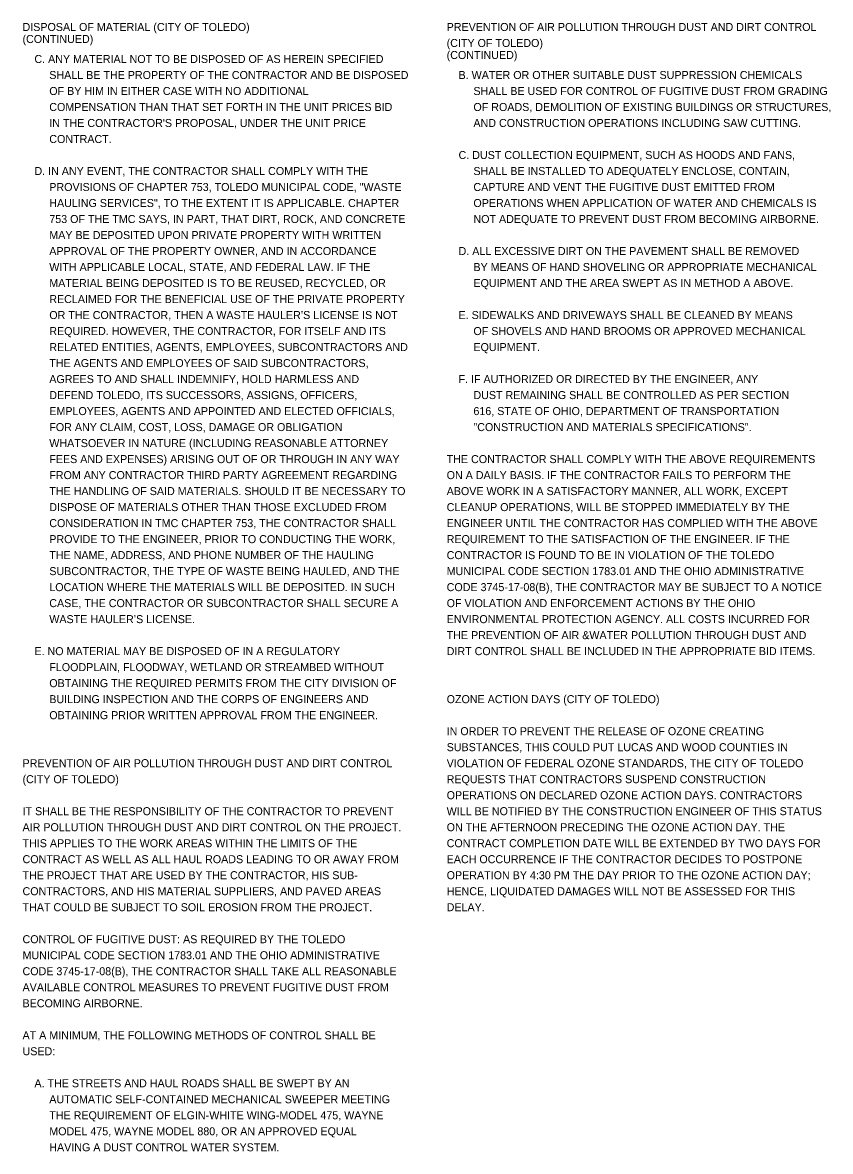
# Model space of a CAD drawing. Extents: x -15.9 to 34, y 0 to 22.
# Drawn here: x -15.92 to -1.79, y 1.02 to 20.77 of the extents above; entities that cross this region are included whole.
import ezdxf

# ---------------------------------------------------------------- set-up
doc = ezdxf.new("R2010")
doc.units = 0
doc.layers.add('SH_Text', color=7, linetype='Continuous')

msp = doc.modelspace()

# ---------------------------------------------------------------- texts
at = {"layer": 'SH_Text'}
for s, p in [('DISPOSAL OF MATERIAL (CITY OF TOLEDO)', (-15.921, 20.621)), ('PREVENTION OF AIR POLLUTION THROUGH DUST AND DIRT CONTROL', (-8.501, 20.621)), ('(CONTINUED)', (-15.921, 20.411)), ('(CITY OF TOLEDO)', (-8.501, 20.341)), ('    C. ANY MATERIAL NOT TO BE DISPOSED OF AS HEREIN SPECIFIED', (-15.921, 20.061)), ('(CONTINUED)', (-8.501, 20.131)), ('         SHALL BE THE PROPERTY OF THE CONTRACTOR AND BE DISPOSED', (-15.921, 19.781)), ('    B. WATER OR OTHER SUITABLE DUST SUPPRESSION CHEMICALS', (-8.501, 19.781)), ('         OF BY HIM IN EITHER CASE WITH NO ADDITIONAL', (-15.921, 19.501)), ('         SHALL BE USED FOR CONTROL OF FUGITIVE DUST FROM GRADING', (-8.501, 19.501)), ('         COMPENSATION THAN THAT SET FORTH IN THE UNIT PRICES BID', (-15.921, 19.221)), ('         OF ROADS, DEMOLITION OF EXISTING BUILDINGS OR STRUCTURES,', (-8.501, 19.221)), ("         IN THE CONTRACTOR'S PROPOSAL, UNDER THE UNIT PRICE", (-15.921, 18.941)), ('         AND CONSTRUCTION OPERATIONS INCLUDING SAW CUTTING.', (-8.501, 18.941)), ('         CONTRACT.', (-15.921, 18.661)), ('    C. DUST COLLECTION EQUIPMENT, SUCH AS HOODS AND FANS, ', (-8.501, 18.381)), ('    D. IN ANY EVENT, THE CONTRACTOR SHALL COMPLY WITH THE', (-15.921, 18.101)), ('         SHALL BE INSTALLED TO ADEQUATELY ENCLOSE, CONTAIN,', (-8.501, 18.101)), ('         PROVISIONS OF CHAPTER 753, TOLEDO MUNICIPAL CODE, "WASTE', (-15.921, 17.821)), ('         CAPTURE AND VENT THE FUGITIVE DUST EMITTED FROM ', (-8.501, 17.821)), ('         HAULING SERVICES", TO THE EXTENT IT IS APPLICABLE. CHAPTER', (-15.921, 17.541)), ('         OPERATIONS WHEN APPLICATION OF WATER AND CHEMICALS IS ', (-8.501, 17.541)), ('         753 OF THE TMC SAYS, IN PART, THAT DIRT, ROCK, AND CONCRETE', (-15.921, 17.261)), ('         NOT ADEQUATE TO PREVENT DUST FROM BECOMING AIRBORNE.', (-8.501, 17.261)), ('         MAY BE DEPOSITED UPON PRIVATE PROPERTY WITH WRITTEN', (-15.921, 16.981)), ('         APPROVAL OF THE PROPERTY OWNER, AND IN ACCORDANCE', (-15.921, 16.701)), ('    D. ALL EXCESSIVE DIRT ON THE PAVEMENT SHALL BE REMOVED', (-8.501, 16.701)), ('         WITH APPLICABLE LOCAL, STATE, AND FEDERAL LAW. IF THE', (-15.921, 16.421)), ('         BY MEANS OF HAND SHOVELING OR APPROPRIATE MECHANICAL ', (-8.501, 16.421)), ('         MATERIAL BEING DEPOSITED IS TO BE REUSED, RECYCLED, OR', (-15.921, 16.141)), ('         EQUIPMENT AND THE AREA SWEPT AS IN METHOD A ABOVE.', (-8.501, 16.141)), ('         RECLAIMED FOR THE BENEFICIAL USE OF THE PRIVATE PROPERTY', (-15.921, 15.861)), ('         OR THE CONTRACTOR, THEN A WASTE HAULER’S LICENSE IS NOT', (-15.921, 15.581)), ('    E. SIDEWALKS AND DRIVEWAYS SHALL BE CLEANED BY MEANS ', (-8.501, 15.581)), ('         REQUIRED. HOWEVER, THE CONTRACTOR, FOR ITSELF AND ITS', (-15.921, 15.301)), ('         OF SHOVELS AND HAND BROOMS OR APPROVED MECHANICAL ', (-8.501, 15.301)), ('         RELATED ENTITIES, AGENTS, EMPLOYEES, SUBCONTRACTORS AND', (-15.921, 15.021)), ('         EQUIPMENT.', (-8.501, 15.021)), ('         THE AGENTS AND EMPLOYEES OF SAID SUBCONTRACTORS,', (-15.921, 14.741)), ('         AGREES TO AND SHALL INDEMNIFY, HOLD HARMLESS AND', (-15.921, 14.461)), ('    F. IF AUTHORIZED OR DIRECTED BY THE ENGINEER, ANY ', (-8.501, 14.461)), ('         DEFEND TOLEDO, ITS SUCCESSORS, ASSIGNS, OFFICERS,', (-15.921, 14.181)), ('         DUST REMAINING SHALL BE CONTROLLED AS PER SECTION ', (-8.501, 14.181)), ('         EMPLOYEES, AGENTS AND APPOINTED AND ELECTED OFFICIALS,', (-15.921, 13.901)), ('         616, STATE OF OHIO, DEPARTMENT OF TRANSPORTATION ', (-8.501, 13.901)), ('         FOR ANY CLAIM, COST, LOSS, DAMAGE OR OBLIGATION', (-15.921, 13.621)), ('         "CONSTRUCTION AND MATERIALS SPECIFICATIONS".', (-8.501, 13.621)), ('         WHATSOEVER IN NATURE (INCLUDING REASONABLE ATTORNEY', (-15.921, 13.341)), ('         FEES AND EXPENSES) ARISING OUT OF OR THROUGH IN ANY WAY', (-15.921, 13.061)), ('THE CONTRACTOR SHALL COMPLY WITH THE ABOVE REQUIREMENTS', (-8.501, 13.061)), ('         FROM ANY CONTRACTOR THIRD PARTY AGREEMENT REGARDING', (-15.921, 12.781)), ('ON A DAILY BASIS. IF THE CONTRACTOR FAILS TO PERFORM THE', (-8.501, 12.781)), ('         THE HANDLING OF SAID MATERIALS. SHOULD IT BE NECESSARY TO', (-15.921, 12.501)), ('ABOVE WORK IN A SATISFACTORY MANNER, ALL WORK, EXCEPT', (-8.501, 12.501)), ('         DISPOSE OF MATERIALS OTHER THAN THOSE EXCLUDED FROM', (-15.921, 12.221)), ('CLEANUP OPERATIONS, WILL BE STOPPED IMMEDIATELY BY THE', (-8.501, 12.221)), ('         CONSIDERATION IN TMC CHAPTER 753, THE CONTRACTOR SHALL', (-15.921, 11.941)), ('ENGINEER UNTIL THE CONTRACTOR HAS COMPLIED WITH THE ABOVE', (-8.501, 11.941)), ('         PROVIDE TO THE ENGINEER, PRIOR TO CONDUCTING THE WORK,', (-15.921, 11.661)), ('REQUIREMENT TO THE SATISFACTION OF THE ENGINEER. IF THE', (-8.501, 11.661)), ('         THE NAME, ADDRESS, AND PHONE NUMBER OF THE HAULING', (-15.921, 11.381)), ('CONTRACTOR IS FOUND TO BE IN VIOLATION OF THE TOLEDO', (-8.501, 11.381)), ('         SUBCONTRACTOR, THE TYPE OF WASTE BEING HAULED, AND THE', (-15.921, 11.101)), ('MUNICIPAL CODE SECTION 1783.01 AND THE OHIO ADMINISTRATIVE', (-8.501, 11.101)), ('         LOCATION WHERE THE MATERIALS WILL BE DEPOSITED. IN SUCH', (-15.921, 10.821)), ('CODE 3745-17-08(B), THE CONTRACTOR MAY BE SUBJECT TO A NOTICE', (-8.501, 10.821)), ('         CASE, THE CONTRACTOR OR SUBCONTRACTOR SHALL SECURE A', (-15.921, 10.541)), ('OF VIOLATION AND ENFORCEMENT ACTIONS BY THE OHIO', (-8.501, 10.541)), ('         WASTE HAULER’S LICENSE.', (-15.921, 10.261)), ('ENVIRONMENTAL PROTECTION AGENCY. ALL COSTS INCURRED FOR', (-8.501, 10.261)), ('THE PREVENTION OF AIR &WATER POLLUTION THROUGH DUST AND', (-8.501, 9.981)), ('    E. NO MATERIAL MAY BE DISPOSED OF IN A REGULATORY', (-15.921, 9.701)), ('DIRT CONTROL SHALL BE INCLUDED IN THE APPROPRIATE BID ITEMS.', (-8.501, 9.701)), ('         FLOODPLAIN, FLOODWAY, WETLAND OR STREAMBED WITHOUT', (-15.921, 9.421)), ('         OBTAINING THE REQUIRED PERMITS FROM THE CITY DIVISION OF', (-15.921, 9.141)), ('         BUILDING INSPECTION AND THE CORPS OF ENGINEERS AND', (-15.921, 8.861)), ('OZONE ACTION DAYS (CITY OF TOLEDO)', (-8.501, 8.861)), ('         OBTAINING PRIOR WRITTEN APPROVAL FROM THE ENGINEER.', (-15.921, 8.581)), ('IN ORDER TO PREVENT THE RELEASE OF OZONE CREATING', (-8.501, 8.301)), ('SUBSTANCES, THIS COULD PUT LUCAS AND WOOD COUNTIES IN', (-8.501, 8.021)), ('PREVENTION OF AIR POLLUTION THROUGH DUST AND DIRT CONTROL', (-15.921, 7.741)), ('VIOLATION OF FEDERAL OZONE STANDARDS, THE CITY OF TOLEDO', (-8.501, 7.741)), ('(CITY OF TOLEDO)', (-15.921, 7.461)), ('REQUESTS THAT CONTRACTORS SUSPEND CONSTRUCTION', (-8.501, 7.461)), ('OPERATIONS ON DECLARED OZONE ACTION DAYS. CONTRACTORS', (-8.501, 7.181)), ('IT SHALL BE THE RESPONSIBILITY OF THE CONTRACTOR TO PREVENT', (-15.921, 6.901)), ('WILL BE NOTIFIED BY THE CONSTRUCTION ENGINEER OF THIS STATUS', (-8.501, 6.901)), ('AIR POLLUTION THROUGH DUST AND DIRT CONTROL ON THE PROJECT.', (-15.921, 6.621)), ('ON THE AFTERNOON PRECEDING THE OZONE ACTION DAY. THE', (-8.501, 6.621)), ('THIS APPLIES TO THE WORK AREAS WITHIN THE LIMITS OF THE', (-15.921, 6.341)), ('CONTRACT COMPLETION DATE WILL BE EXTENDED BY TWO DAYS FOR', (-8.501, 6.341)), ('CONTRACT AS WELL AS ALL HAUL ROADS LEADING TO OR AWAY FROM', (-15.921, 6.061)), ('EACH OCCURRENCE IF THE CONTRACTOR DECIDES TO POSTPONE', (-8.501, 6.061)), ('THE PROJECT THAT ARE USED BY THE CONTRACTOR, HIS SUB-', (-15.921, 5.781)), ('OPERATION BY 4:30 PM THE DAY PRIOR TO THE OZONE ACTION DAY;', (-8.501, 5.781)), ('CONTRACTORS, AND HIS MATERIAL SUPPLIERS, AND PAVED AREAS', (-15.921, 5.501)), ('HENCE, LIQUIDATED DAMAGES WILL NOT BE ASSESSED FOR THIS', (-8.501, 5.501)), ('THAT COULD BE SUBJECT TO SOIL EROSION FROM THE PROJECT.', (-15.921, 5.221)), ('DELAY.', (-8.501, 5.221)), ('CONTROL OF FUGITIVE DUST: AS REQUIRED BY THE TOLEDO', (-15.921, 4.661)), ('MUNICIPAL CODE SECTION 1783.01 AND THE OHIO ADMINISTRATIVE', (-15.921, 4.381)), ('CODE 3745-17-08(B), THE CONTRACTOR SHALL TAKE ALL REASONABLE', (-15.921, 4.101)), ('AVAILABLE CONTROL MEASURES TO PREVENT FUGITIVE DUST FROM', (-15.921, 3.821)), ('BECOMING AIRBORNE.', (-15.921, 3.541)), ('AT A MINIMUM, THE FOLLOWING METHODS OF CONTROL SHALL BE', (-15.921, 2.981)), ('USED:', (-15.921, 2.701)), ('    A. THE STREETS AND HAUL ROADS SHALL BE SWEPT BY AN', (-15.921, 2.141)), ('         AUTOMATIC SELF-CONTAINED MECHANICAL SWEEPER MEETING', (-15.921, 1.861)), ('         THE REQUIREMENT OF ELGIN-WHITE WING-MODEL 475, WAYNE ', (-15.921, 1.581)), ('         MODEL 475, WAYNE MODEL 880, OR AN APPROVED EQUAL', (-15.921, 1.301)), ('         HAVING A DUST CONTROL WATER SYSTEM.', (-15.921, 1.021))]:
    msp.add_text(s, height=0.14, dxfattribs=at).set_placement(p)

doc.saveas('drawing.dxf')
